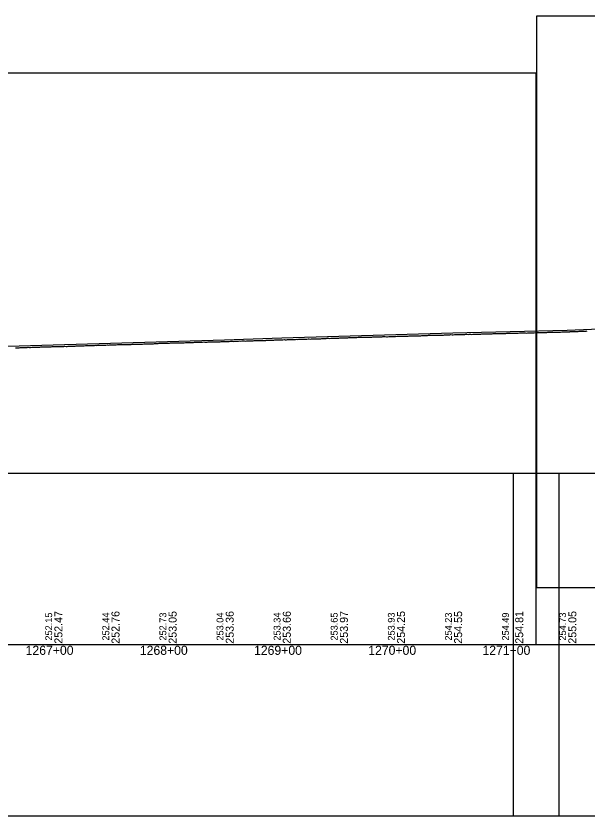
# Model space of a CAD drawing. Extents: x 2898 to 49495, y -15038 to -13538.
# Drawn here: x 16021 to 16521, y -15038 to -14338 of the extents above; entities that cross this region are included whole.
import ezdxf

# ---------------------------------------------------------------- set-up
doc = ezdxf.new("R2010")
doc.units = 0
for name, color, linetype in [('RD_DDB_Profile_EX', 7, 'Continuous'), ('RD_DDB_Profile_PR', 7, 'Continuous'), ('RD_DDB_StaTX', 7, 'Continuous'), ('RD_DDB_StripGrade', 7, 'Continuous'), ('RD_GPK_Profile_Cell', 7, 'Continuous'), ('RD_SHT_ShtClip', 7, 'Continuous')]:
    doc.layers.add(name, color=color, linetype=linetype)

msp = doc.modelspace()

# ---------------------------------------------------------------- linework, layer by layer
at = {"layer": 'RD_DDB_Profile_EX'}
for points in [[(16364.09, -14618.48), (16365.09, -14618.43), (16366.09, -14618.38), (16367.08, -14618.43), (16368.09, -14618.38), (16369.09, -14618.38), (16370.09, -14618.33), (16371.09, -14618.32), (16372.08, -14618.23), (16373.09, -14618.18), (16374.08, -14618.23), (16375.09, -14618.18), (16376.09, -14618.03), (16377.08, -14618.03), (16378.09, -14617.98), (16379.09, -14617.98), (16380.09, -14617.93), (16381.08, -14617.92), (16382.08, -14617.88), (16383.09, -14617.88), (16384.09, -14617.87), (16385.09, -14617.82), (16386.08, -14617.78), (16387.09, -14617.68), (16388.08, -14617.73), (16389.09, -14617.82), (16390.09, -14617.77), (16391.08, -14617.68), (16392.09, -14617.68), (16393.08, -14617.63), (16394.09, -14617.67), (16395.09, -14617.62), (16396.08, -14617.43), (16397.09, -14617.38), (16397.62, -14617.38), (16398.62, -14617.37), (16399.62, -14617.32), (16400.63, -14617.33), (16401.62, -14617.27), (16402.62, -14617.32), (16403.62, -14617.32), (16404.62, -14617.27), (16405.62, -14617.22), (16406.62, -14617.27), (16407.62, -14617.17), (16408.62, -14617.12), (16409.62, -14617.22), (16410.62, -14617.22), (16411.62, -14617.17), (16412.62, -14617.12), (16413.62, -14617.07), (16414.62, -14616.92), (16415.62, -14616.97), (16416.62, -14617.02), (16417.62, -14616.92), (16418.62, -14616.92), (16419.62, -14617.02), (16420.62, -14616.97), (16421.62, -14616.87), (16422.61, -14616.92), (16423.62, -14616.87), (16424.61, -14616.77), (16425.62, -14616.72), (16426.61, -14616.82), (16427.62, -14616.87), (16428.62, -14616.62), (16429.62, -14616.57), (16430.62, -14616.67), (16431.61, -14616.62), (16432.61, -14616.62), (16433.61, -14616.67), (16434.61, -14616.57), (16435.62, -14616.47), (16436.61, -14616.47), (16437.62, -14616.52), (16438.61, -14616.37), (16439.62, -14616.32), (16440.61, -14616.37), (16441.62, -14616.37), (16442.62, -14616.32), (16443.62, -14616.37), (16444.25, -14616.3), (16444.62, -14616.27), (16445.62, -14616.22), (16446.61, -14616.22), (16447.55, -14616.22), (16448.76, -14616.18), (16449.55, -14616.22), (16450.55, -14616.12), (16451.55, -14616.07), (16452.55, -14616.02), (16453.55, -14616.02), (16454.54, -14616.07), (16455.55, -14616.07), (16456.55, -14616.07), (16457.55, -14616.02), (16458.55, -14615.97), (16459.54, -14615.92), (16460.55, -14615.92), (16461.55, -14615.82), (16462.55, -14615.82)], [(16462.55, -14615.82), (16463.55, -14615.82), (16464.55, -14615.82), (16465.55, -14615.77), (16466.55, -14615.72), (16467.55, -14615.92), (16468.55, -14615.82), (16469.55, -14615.67), (16470.55, -14615.62), (16471.55, -14615.62), (16472.55, -14615.62), (16473.55, -14615.57), (16474.55, -14615.57), (16475.55, -14615.52), (16476.55, -14615.52), (16477.55, -14615.47), (16478.55, -14615.52), (16479.55, -14615.37), (16480.54, -14615.37), (16481.55, -14615.42), (16482.55, -14615.47), (16483.55, -14615.47), (16484.55, -14615.37), (16485.54, -14615.37), (16486.55, -14615.17), (16487.55, -14615.17), (16488.55, -14615.22), (16489.55, -14615.17), (16490.54, -14615.07), (16491.55, -14615.07), (16492.55, -14614.97), (16493.55, -14615.02), (16494.55, -14615.02), (16495.54, -14615.02), (16496.55, -14615.02), (16497.55, -14614.97), (16498.55, -14614.92), (16499.55, -14614.82), (16500.56, -14614.77), (16501.55, -14614.77), (16502.55, -14614.82), (16503.55, -14614.82), (16504.55, -14614.77), (16505.56, -14614.72), (16505.97, -14614.62), (16506.97, -14614.62), (16507.97, -14614.62), (16508.97, -14614.57), (16509.98, -14614.47), (16510.98, -14614.42), (16511.97, -14614.42), (16512.98, -14614.47), (16513.98, -14614.32), (16514.97, -14614.27), (16515.97, -14614.22), (16516.96, -14614.17), (16517.97, -14614.17), (16518.97, -14614.22), (16519.97, -14614.21), (16520.97, -14614.07)], [(16167.11, -14624.33), (16168.11, -14624.33), (16169.1, -14624.28), (16170.11, -14624.23), (16171.1, -14624.18), (16172.1, -14624.18), (16173.1, -14624.08), (16174.1, -14624.08), (16175.11, -14624.08), (16176.1, -14624.08), (16177.11, -14623.93), (16178.1, -14623.93), (16179.1, -14623.98), (16180.11, -14623.93), (16181.1, -14623.93), (16182.11, -14623.88), (16183.1, -14623.78), (16184.1, -14623.73), (16185.1, -14623.69), (16186.1, -14623.73), (16187.11, -14623.78), (16188.1, -14623.73), (16189.11, -14623.68), (16190.1, -14623.58), (16190.45, -14623.58), (16191.45, -14623.63), (16192.45, -14623.58), (16193.45, -14623.53), (16194.45, -14623.58), (16195.45, -14623.53), (16196.45, -14623.48), (16197.45, -14623.43), (16198.45, -14623.48), (16199.45, -14623.43), (16200.45, -14623.33), (16201.45, -14623.33), (16202.44, -14623.33), (16203.45, -14623.28), (16204.44, -14623.28), (16205.45, -14623.18), (16206.44, -14623.18), (16207.44, -14623.18), (16208.45, -14623.13), (16209.44, -14623.03), (16210.44, -14623.03), (16211.45, -14623.17), (16212.45, -14623.07), (16213.44, -14623.02), (16214.45, -14622.98), (16215.44, -14622.87), (16216.45, -14622.82), (16217.44, -14622.87), (16218.44, -14622.82), (16219.44, -14622.77), (16220.44, -14622.82), (16221.44, -14622.87), (16222.44, -14622.77), (16223.44, -14622.67), (16224.44, -14622.62), (16225.44, -14622.62), (16226.44, -14622.57), (16227.44, -14622.57), (16228.44, -14622.57), (16229.43, -14622.52), (16230.44, -14622.42), (16231.43, -14622.37), (16232.43, -14622.42), (16233.44, -14622.42), (16234.44, -14622.27), (16235.44, -14622.32), (16236.44, -14622.42), (16237.43, -14622.47), (16238.44, -14622.27), (16239.44, -14622.27), (16239.87, -14622.2), (16240.43, -14622.12), (16241.44, -14622.12), (16242.43, -14622.12), (16243.52, -14622.12), (16244.53, -14622.07), (16245.71, -14622.01), (16246.52, -14621.97), (16247.53, -14621.92), (16248.04, -14621.89), (16248.52, -14621.87), (16249.53, -14621.87), (16250.52, -14621.92), (16251.59, -14621.86), (16252.52, -14621.82), (16253.52, -14621.77), (16254.53, -14621.72), (16255.52, -14621.67), (16256.53, -14621.77), (16257.52, -14621.72), (16258.52, -14621.62), (16259.53, -14621.67), (16260.53, -14621.62), (16261.52, -14621.52), (16262.52, -14621.57), (16263.53, -14621.62), (16264.52, -14621.62)], [(16264.52, -14621.62), (16265.52, -14621.52), (16266.53, -14621.37), (16267.53, -14621.42), (16268.52, -14621.37), (16269.52, -14621.32), (16270.53, -14621.32), (16271.52, -14621.32), (16272.52, -14621.27), (16273.53, -14621.27), (16274.53, -14621.27), (16275.52, -14621.17), (16276.53, -14621.07), (16277.53, -14621.07), (16278.53, -14621.17), (16279.52, -14621.02), (16280.53, -14620.92), (16281.53, -14620.97), (16282.52, -14620.92), (16283.53, -14620.92), (16284.52, -14620.92), (16285.53, -14620.82), (16286.52, -14620.87), (16287.53, -14620.82), (16288.53, -14620.67), (16289.52, -14620.67), (16290.32, -14620.67), (16291.32, -14620.62), (16292.31, -14620.57), (16293.32, -14620.47), (16294.32, -14620.47), (16295.31, -14620.52), (16296.32, -14620.47), (16297.32, -14620.42), (16298.32, -14620.37), (16299.31, -14620.27), (16300.32, -14620.22), (16301.32, -14620.27), (16302.32, -14620.22), (16303.32, -14620.22), (16304.31, -14620.17), (16305.32, -14620.17), (16306.32, -14620.17), (16307.31, -14620.07), (16308.32, -14620.07), (16309.32, -14620.07), (16310.32, -14620.02), (16311.31, -14619.97), (16312.32, -14619.87), (16313.31, -14619.82), (16314.31, -14619.77), (16315.32, -14619.87), (16316.31, -14619.82), (16317.32, -14619.72), (16318.31, -14619.67), (16319.31, -14619.67), (16320.32, -14619.62), (16321.32, -14619.63), (16322.31, -14619.62), (16323.31, -14619.57), (16324.32, -14619.52), (16325.31, -14619.48), (16326.31, -14619.48), (16327.32, -14619.48), (16328.31, -14619.43), (16329.32, -14619.43), (16330.31, -14619.43), (16331.31, -14619.38), (16332.32, -14619.47), (16333.32, -14619.33), (16334.31, -14619.28), (16335.31, -14619.28), (16336.32, -14619.23), (16337.32, -14619.23), (16338.31, -14619.13), (16339.32, -14619.13), (16340.32, -14619.13), (16341.32, -14619.08), (16342.09, -14619.03), (16343.09, -14619.03), (16344.08, -14619.03), (16345.09, -14619.13), (16346.09, -14619.08), (16347.09, -14618.93), (16348.09, -14618.93), (16349.09, -14618.88), (16350.09, -14618.83), (16351.09, -14618.78), (16352.09, -14618.88), (16353.08, -14618.83), (16354.09, -14618.73), (16355.08, -14618.68), (16356.09, -14618.68), (16357.09, -14618.63), (16358.08, -14618.63), (16359.09, -14618.63), (16360.09, -14618.53), (16361.09, -14618.48), (16362.09, -14618.53), (16363.08, -14618.63), (16364.09, -14618.48)], [(16020.39, -14628.82), (16021.39, -14628.77), (16022.39, -14628.77), (16023.38, -14628.72), (16024.39, -14628.62), (16025.38, -14628.62), (16026.38, -14628.62), (16027.38, -14628.67), (16028.38, -14628.62), (16029.38, -14628.47), (16030.38, -14628.47), (16031.38, -14628.37), (16032.54, -14628.42), (16033.54, -14628.47), (16034.54, -14628.37), (16035.54, -14628.32), (16036.54, -14628.27), (16037.54, -14628.32), (16038.53, -14628.27), (16039.54, -14628.22), (16040.54, -14628.17), (16041.54, -14628.12), (16042.54, -14628.07), (16043.53, -14628.07), (16044.54, -14628.02), (16045.54, -14628.02), (16046.54, -14628.07), (16047.54, -14628.02), (16048.53, -14627.97), (16049.53, -14627.97), (16050.54, -14627.92), (16051.54, -14627.82), (16052.54, -14627.72), (16053.53, -14627.72), (16054.53, -14627.77), (16055.54, -14627.72), (16056.54, -14627.77), (16057.54, -14627.72), (16058.54, -14627.67), (16059.53, -14627.62), (16060.54, -14627.52), (16061.54, -14627.57), (16062.54, -14627.57), (16063.55, -14627.47), (16064.54, -14627.52), (16065.54, -14627.52), (16066.54, -14627.42), (16067.54, -14627.32)], [(16067.54, -14627.32), (16068.55, -14627.37), (16069.54, -14627.32), (16070.54, -14627.22), (16071.54, -14627.27), (16072.54, -14627.32), (16073.55, -14627.17), (16074.54, -14627.12), (16075.54, -14627.07), (16076.54, -14627.12), (16077.54, -14627.17), (16078.55, -14627.02), (16079.54, -14627.02), (16080.54, -14626.97), (16081.54, -14626.92), (16082.54, -14626.87), (16083.55, -14626.87), (16084.54, -14626.82), (16085.53, -14626.78), (16086.53, -14626.68), (16087.53, -14626.77), (16088.54, -14626.82), (16089.54, -14626.72), (16090.53, -14626.63), (16091.54, -14626.67), (16092.53, -14626.58), (16093.53, -14626.53), (16094.54, -14626.53), (16095.53, -14626.48), (16096.54, -14626.53), (16097.54, -14626.48), (16098.54, -14626.43), (16099.54, -14626.43), (16100.53, -14626.33), (16101.54, -14626.37), (16102.53, -14626.33), (16103.54, -14626.28), (16104.54, -14626.18), (16105.53, -14626.18), (16106.54, -14626.23), (16107.54, -14626.18), (16108.53, -14626.18), (16109.53, -14626.03), (16110.54, -14626.03), (16111.54, -14625.98), (16112.53, -14625.93), (16113.54, -14625.98), (16114.54, -14625.98), (16115.54, -14625.78), (16116.53, -14625.78), (16117.54, -14625.83), (16118.54, -14625.78), (16119.53, -14625.78), (16120.54, -14625.83), (16121.54, -14625.78), (16122.54, -14625.63), (16123.53, -14625.68), (16124.54, -14625.63), (16125.54, -14625.63), (16126.53, -14625.58), (16127.54, -14625.53), (16128.53, -14625.48), (16129.54, -14625.48), (16130.54, -14625.48), (16131.54, -14625.48), (16132.54, -14625.43), (16133.53, -14625.38), (16134.54, -14625.33), (16135.54, -14625.28), (16136.54, -14625.23), (16137.54, -14625.23), (16138.53, -14625.23), (16139.11, -14625.18), (16140.1, -14625.23), (16141.1, -14625.23), (16142.1, -14625.03), (16143.11, -14624.98), (16144.1, -14625.03), (16145.1, -14624.98), (16146.11, -14624.88), (16147.1, -14624.88), (16148.1, -14624.88), (16149.1, -14624.83), (16150.11, -14624.78), (16151.1, -14624.73), (16152.1, -14624.78), (16153.11, -14624.83), (16154.1, -14624.73), (16155.1, -14624.63), (16156.11, -14624.58), (16157.11, -14624.53), (16158.1, -14624.58), (16159.1, -14624.53), (16160.11, -14624.43), (16161.1, -14624.48), (16162.1, -14624.48), (16163.11, -14624.43), (16164.1, -14624.38), (16165.1, -14624.48), (16166.1, -14624.38), (16167.11, -14624.33)]]:
    msp.add_lwpolyline(points, dxfattribs=at)
at = {"layer": 'RD_DDB_Profile_PR'}
msp.add_lwpolyline([(16003.38, -14627.72), (16053.38, -14626.12), (16103.38, -14624.68), (16153.38, -14623.2), (16203.38, -14621.68), (16253.38, -14620.17), (16303.38, -14618.62), (16353.38, -14617.2), (16403.38, -14615.72), (16453.38, -14614.42), (16503.38, -14613.22), (16553.38, -14611.24), (16603.38, -14609.37), (16653.38, -14608.29), (16703.38, -14607.35), (16753.38, -14606.06), (16803.38, -14604.27), (16853.38, -14602.2), (16903.38, -14600.36), (16953.38, -14598.62), (17003.38, -14597.42), (17053.38, -14595.8)], dxfattribs=at)
at = {"layer": 'RD_GPK_Profile_Cell'}
msp.add_line((2976.05, -14888.47), (48721.13, -14888.47), dxfattribs=at)
at = {"layer": 'RD_SHT_ShtClip'}
for points in [[(17976.22, -14838.47), (17976.22, -14338.47), (17976.22, -14338.47), (16476.38, -14338.47), (16476.38, -14838.47)], [(16476.22, -14888.47), (16476.22, -14388.47), (16476.22, -14388.47), (14976.38, -14388.47), (14976.38, -14888.47)], [(14956.38, -14738.47), (16496.05, -14738.47), (16496.05, -15038.47), (14956.38, -15038.47)], [(16456.38, -14738.47), (17996.05, -14738.47), (17996.05, -15038.47), (16456.38, -15038.47)]]:
    msp.add_lwpolyline(points, close=True, dxfattribs=at)

# ---------------------------------------------------------------- texts
at = {"layer": 'RD_DDB_StaTX'}
for s, p in [('1267+00', (16029.18, -14897.47)), ('1268+00', (16129.18, -14897.47)), ('1269+00', (16229.18, -14897.47)), ('1270+00', (16329.18, -14897.47)), ('1271+00', (16429.18, -14897.47))]:
    msp.add_text(s, height=8, dxfattribs=at).set_placement(p)
at = {"layer": 'RD_DDB_StripGrade'}
for s, height, p in [('252.15', 6, (16052.38, -14884.98)), ('252.47', 7, (16061.38, -14887.72)), ('252.44', 6, (16102.38, -14884.98)), ('252.76', 7, (16111.38, -14887.72)), ('252.73', 6, (16152.38, -14884.98)), ('253.05', 7, (16161.38, -14887.72)), ('253.04', 6, (16202.38, -14884.98)), ('253.36', 7, (16211.38, -14887.72)), ('253.34', 6, (16252.38, -14884.98)), ('253.66', 7, (16261.38, -14887.72)), ('253.65', 6, (16302.38, -14884.98)), ('253.97', 7, (16311.38, -14887.72)), ('253.93', 6, (16352.38, -14884.98)), ('254.25', 7, (16361.38, -14887.72)), ('254.23', 6, (16402.38, -14884.98)), ('254.55', 7, (16411.38, -14887.72)), ('254.49', 6, (16452.38, -14884.98)), ('254.81', 7, (16464.88, -14887.72)), ('254.73', 6, (16502.38, -14884.98)), ('255.05', 7, (16511.38, -14887.72))]:
    msp.add_text(s, height=height, rotation=90, dxfattribs=at).set_placement(p)

doc.saveas('drawing.dxf')
